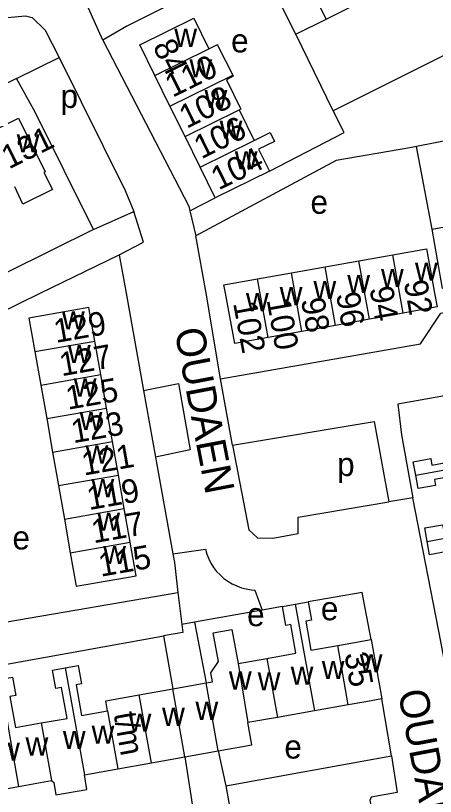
# Model space of a CAD drawing. Extents: x 157794 to 159375, y 380877 to 382306.
# Drawn here: x 158437 to 158508.3, y 381414.5 to 381547.1 of the extents above; entities that cross this region are included whole.
import ezdxf

# ---------------------------------------------------------------- set-up
doc = ezdxf.new("R2010")
doc.units = 0
for name, color, linetype in [('BLT_Basislijn', 7, 'Continuous'), ('BLT_Bebouwing', 7, 'Continuous'), ('BLT_Centroide', 7, 'Continuous'), ('BLT_Huisnummer', 7, 'Continuous'), ('BLT_Huisnummer_ tussenligend', 7, 'Continuous'), ('BLT_Huisnummer_reeks', 7, 'Continuous'), ('BLT_Onderverdeling_panden', 7, 'Continuous'), ('BLT_Straatnaam', 7, 'Continuous')]:
    doc.layers.add(name, color=color, linetype=linetype)

msp = doc.modelspace()

# ---------------------------------------------------------------- linework, layer by layer
at = {"layer": 'BLT_Basislijn'}
for p, q in [((158519.87, 381545.44), (158490.95, 381530.99)), ((158490.95, 381530.99), (158484.57, 381543.99)), ((158437.14, 381536.48), (158444.4, 381540.04)), ((158524.33, 381528.74), (158505.11, 381524.89)), ((158507.73, 381510.87), (158505.11, 381524.89)), ((158466.62, 381513.98), (158470.92, 381516.18)), ((158450.23, 381510.78), (158457.08, 381513.88)), ((158466.62, 381513.98), (158467.63, 381509.74)), ((158473.82, 381474.14), (158471.81, 381485.4)), ((158458.75, 381483.43), (158460.77, 381472.12)), ((158460.77, 381472.12), (158463.72, 381455.67)), ((158504.49, 381465.23), (158500.38, 381464.53)), ((158463.72, 381455.67), (158469.25, 381456.46)), ((158464.58, 381449.11), (158465.22, 381443.65)), ((158477.65, 381449.54), (158478.89, 381446.13)), ((158482.31, 381446.75), (158478.89, 381446.13)), ((158478.89, 381446.13), (158467.4, 381444.05)), ((158467.4, 381444.05), (158465.22, 381443.65)), ((158467.4, 381444.05), (158469.36, 381433.75)), ((158462.15, 381441.73), (158463.68, 381432.73)), ((158500.87, 381421.37), (158499.19, 381431.02)), ((158465.74, 381421.18), (158467.36, 381410.72)), ((158471.43, 381422.2), (158472.71, 381416.28)), ((158472.71, 381416.28), (158500.87, 381421.37))]:
    msp.add_line(p, q, dxfattribs=at)
for points in [[(158451.81, 381542.95), (158449.11, 381549.01), (158449.43, 381551.81), (158451.61, 381553.86), (158561.13, 381600.93)], [(158478.22, 381556.59), (158477.09, 381556.02), (158455.91, 381545.38), (158451.81, 381542.95)], [(158432.05, 381545.11), (158435.65, 381546.85), (158438.67, 381547.13), (158439.79, 381546.85), (158442.01, 381544.7), (158444.4, 381540.04)], [(158451.81, 381542.95), (158466.43, 381514.78), (158466.62, 381513.98)], [(158444.4, 381540.04), (158455.63, 381517.4), (158457.08, 381513.88)], [(158437.14, 381536.48), (158402.44, 381519.39), (158402.32, 381519.33)], [(158450.23, 381510.78), (158440.35, 381530.76), (158437.14, 381536.48)], [(158480.1, 381520.71), (158492.78, 381527.28), (158490.95, 381530.99)], [(158505.11, 381524.89), (158503.95, 381524.66), (158491.43, 381522.5), (158467.63, 381509.74)], [(158454.58, 381506.47), (158458.75, 381508.66), (158457.08, 381513.88)], [(158450.23, 381510.78), (158428.38, 381500), (158416.79, 381493.84)], [(158471.81, 381485.4), (158469.37, 381500), (158467.63, 381509.74)], [(158428.64, 381479.68), (158426.62, 381492.06), (158426.74, 381492.89), (158441.15, 381500), (158454.58, 381506.47)], [(158454.58, 381506.47), (158455.78, 381500), (158458.75, 381483.43)], [(158471.81, 381485.4), (158505.79, 381491.35), (158509.22, 381496.6), (158527.38, 381500), (158562.57, 381506.47)], [(158529.66, 381491.41), (158517.05, 381489.15), (158513.32, 381484.4), (158511.45, 381482.81), (158501.9, 381481.1), (158502.53, 381475.91), (158504.49, 381465.23)], [(158458.75, 381483.43), (158464.65, 381484.62), (158466.65, 381473.34), (158460.77, 381472.12)], [(158473.82, 381474.14), (158497.89, 381478.15), (158500.38, 381464.53)], [(158473.82, 381474.14), (158476.63, 381459.78), (158478.07, 381458.43), (158480.71, 381458.36), (158485, 381459.16), (158484.98, 381461.91), (158500.38, 381464.53)], [(158516.54, 381401.63), (158509.27, 381440.5), (158504.49, 381465.23)], [(158463.72, 381455.67), (158463.98, 381454.24), (158464.58, 381449.11)], [(158469.25, 381456.46), (158469.49, 381455.64), (158469.8, 381454.85), (158470.18, 381454.1), (158470.64, 381453.38), (158471.15, 381452.71), (158471.74, 381452.09), (158472.37, 381451.52), (158473.06, 381451.02), (158473.79, 381450.59), (158474.55, 381450.22), (158475.35, 381449.93), (158476.17, 381449.72), (158477.01, 381449.59), (158477.65, 381449.54)], [(158434.46, 381449.35), (158435.52, 381444.13), (158464.58, 381449.11)], [(158497.38, 381441.14), (158495.88, 381449.11), (158486.67, 381447.53)], [(158465.22, 381443.65), (158465.38, 381442.34), (158462.15, 381441.73)], [(158404.63, 381433.72), (158404.24, 381435.67), (158426.55, 381439.67), (158427.12, 381439.4), (158428.2, 381435.71), (158428.84, 381435.74), (158461.58, 381441.62), (158462.15, 381441.73)], [(158500.87, 381421.37), (158501.78, 381415.14), (158497.38, 381414.35), (158497.19, 381413.77), (158498.73, 381406.43)], [(158472.71, 381416.28), (158474.45, 381406.5), (158472.22, 381406.1), (158472.99, 381401.84)]]:
    msp.add_lwpolyline(points, dxfattribs=at)
at = {"layer": 'BLT_Bebouwing'}
for p, q in [((158489.75, 381546.57), (158494.93, 381549.15)), ((158484.57, 381543.99), (158489.75, 381546.57)), ((158463.22, 381531.78), (158460.66, 381536.98)), ((158465.79, 381526.58), (158463.22, 381531.78)), ((158474.97, 381531.11), (158477.54, 381525.91)), ((158468.35, 381521.38), (158465.79, 381526.58)), ((158470.92, 381516.18), (158468.35, 381521.38)), ((158480.1, 381520.71), (158470.92, 381516.18)), ((158507.73, 381510.87), (158513.4, 381511.87)), ((158495.32, 381505.49), (158501.05, 381506.51)), ((158489.58, 381504.47), (158495.32, 381505.49)), ((158478.11, 381502.44), (158483.84, 381503.46)), ((158483.84, 381503.46), (158489.58, 381504.47)), ((158497.08, 381495.55), (158491.35, 381494.51)), ((158502.81, 381496.59), (158497.08, 381495.55)), ((158491.35, 381494.51), (158485.61, 381493.47)), ((158485.61, 381493.47), (158479.88, 381492.44)), ((158451.47, 381486.15), (158450.46, 381491.85)), ((158440.28, 381490.06), (158441.28, 381484.36)), ((158452.47, 381480.46), (158451.47, 381486.15)), ((158441.28, 381484.36), (158442.29, 381478.67)), ((158453.47, 381474.76), (158452.47, 381480.46)), ((158442.29, 381478.67), (158443.29, 381472.97)), ((158454.47, 381469.06), (158453.47, 381474.76)), ((158443.29, 381472.97), (158444.29, 381467.27)), ((158455.47, 381463.37), (158454.47, 381469.06)), ((158444.29, 381467.27), (158445.29, 381461.58)), ((158456.47, 381457.67), (158455.47, 381463.37)), ((158445.29, 381461.58), (158446.29, 381455.88)), ((158482.31, 381446.75), (158484.49, 381447.14)), ((158484.49, 381447.14), (158486.67, 381447.53)), ((158491.72, 381440.13), (158497.38, 381441.14)), ((158497.38, 381441.14), (158499.19, 381431.02)), ((158474.79, 381437.04), (158479.69, 381437.91)), ((158463.68, 381432.73), (158469.36, 381433.75)), ((158457.99, 381431.72), (158463.68, 381432.73)), ((158493.5, 381430.01), (158487.74, 381429)), ((158481.48, 381427.9), (158476.43, 381427.02)), ((158487.74, 381429), (158481.48, 381427.9)), ((158460.06, 381420.16), (158465.74, 381421.18)), ((158465.74, 381421.18), (158471.43, 381422.2)), ((158454.38, 381419.15), (158460.06, 381420.16)), ((158448.69, 381418.13), (158454.38, 381419.15)), ((158437.5, 381416.13), (158443.12, 381417.14))]:
    msp.add_line(p, q, dxfattribs=at)
for points in [[(158484.57, 381543.99), (158484.04, 381545.06), (158482.33, 381548.5), (158480.07, 381553.05)], [(158460.66, 381536.98), (158458.09, 381542.18), (158467.27, 381546.71), (158469.83, 381541.51)], [(158469.83, 381541.51), (158471.28, 381542.21), (158471.37, 381542.02), (158473.89, 381537)], [(158473.89, 381537), (158473.96, 381536.84), (158472.8, 381536.26), (158475.23, 381531.24), (158474.97, 381531.11)], [(158432.35, 381527.15), (158437.52, 381529.73), (158442.05, 381520.62), (158441.81, 381520.5), (158443.25, 381517.6), (158438.24, 381515.11), (158436.88, 381518.05)], [(158477.54, 381525.91), (158480.23, 381527.26), (158480.95, 381525.75), (158478.27, 381524.43), (158480.1, 381520.71)], [(158515.2, 381501.75), (158509.52, 381500.75), (158508.65, 381505.67), (158507.73, 381510.87)], [(158501.05, 381506.51), (158506.79, 381507.53), (158507.7, 381502.55), (158508.15, 381500), (158508.59, 381497.64), (158502.81, 381496.59)], [(158479.88, 381492.44), (158474.23, 381491.41), (158472.63, 381500), (158472.37, 381501.42), (158478.11, 381502.44)], [(158450.46, 381491.85), (158449.46, 381497.55), (158439.28, 381495.76), (158440.28, 381490.06)], [(158504.95, 381469.06), (158504.54, 381471.32), (158507.51, 381471.86), (158507.71, 381470.76), (158512.84, 381471.69), (158511.91, 381476.82)], [(158514.08, 381464.85), (158513.28, 381469.23), (158508.13, 381468.29), (158508.31, 381467.32), (158505.37, 381466.79), (158504.95, 381469.06)], [(158506.9, 381457.81), (158506.49, 381460.08), (158509.52, 381460.63), (158509.72, 381459.53), (158514.87, 381460.46), (158514.08, 381464.85)], [(158446.29, 381455.88), (158447.29, 381450.18), (158457.47, 381451.97), (158456.47, 381457.67)], [(158516.08, 381453.58), (158515.29, 381457.93), (158510.16, 381456.99), (158510.32, 381456.08), (158507.32, 381455.53), (158506.9, 381457.81)], [(158479.69, 381437.91), (158484.59, 381438.79), (158483.72, 381443.68), (158482.89, 381443.53), (158482.31, 381446.75)], [(158486.67, 381447.53), (158487.23, 381444.4), (158486.27, 381444.22), (158487.15, 381439.31), (158491.72, 381440.13)], [(158469.36, 381433.75), (158470.43, 381433.94), (158470.15, 381435.49), (158471.46, 381437.37), (158470.58, 381442.26), (158473.75, 381442.82), (158474.79, 381437.04)], [(158441.37, 381426.94), (158445.76, 381427.73), (158444.82, 381432.98), (158443.81, 381432.8), (158443.25, 381435.93), (158445.44, 381436.32)], [(158445.44, 381436.32), (158447.62, 381436.71), (158448.18, 381433.58), (158447.27, 381433.42), (158448.2, 381428.2), (158452.62, 381428.99)], [(158434.25, 381434.31), (158436.48, 381434.71), (158437.03, 381431.61), (158436.04, 381431.43), (158436.98, 381426.16), (158441.37, 381426.94)], [(158452.62, 381428.99), (158452.31, 381430.7), (158457.99, 381431.72)], [(158499.19, 381431.02), (158496.47, 381430.53), (158493.5, 381430.01)], [(158471.43, 381422.2), (158477.11, 381423.21), (158476.43, 381427.02)], [(158431.31, 381418.84), (158431.97, 381415.14), (158437.5, 381416.13)], [(158443.12, 381417.14), (158443.48, 381416.83), (158443.86, 381414.71), (158449.09, 381415.65), (158448.69, 381418.13)]]:
    msp.add_lwpolyline(points, dxfattribs=at)
at = {"layer": 'BLT_Onderverdeling_panden'}
for p, q in [((158489.75, 381546.57), (158485.25, 381555.62)), ((158460.66, 381536.98), (158469.83, 381541.51)), ((158463.22, 381531.78), (158473.89, 381537)), ((158465.79, 381526.58), (158474.97, 381531.11)), ((158468.35, 381521.38), (158477.54, 381525.91)), ((158502.81, 381496.59), (158501.05, 381506.51)), ((158497.08, 381495.55), (158495.32, 381505.49)), ((158485.61, 381493.47), (158483.84, 381503.46)), ((158491.35, 381494.51), (158489.58, 381504.47)), ((158479.88, 381492.44), (158478.11, 381502.44)), ((158440.28, 381490.06), (158450.46, 381491.85)), ((158441.28, 381484.36), (158451.47, 381486.15)), ((158442.29, 381478.67), (158452.47, 381480.46)), ((158443.29, 381472.97), (158453.47, 381474.76)), ((158504.95, 381469.06), (158522.94, 381472.32)), ((158444.29, 381467.27), (158454.47, 381469.06)), ((158445.29, 381461.58), (158455.47, 381463.37)), ((158506.9, 381457.81), (158524.98, 381461.09)), ((158446.29, 381455.88), (158456.47, 381457.67)), ((158484.49, 381447.14), (158487.74, 381429)), ((158493.5, 381430.01), (158491.72, 381440.13)), ((158479.69, 381437.91), (158481.48, 381427.9)), ((158445.44, 381436.32), (158448.69, 381418.13)), ((158474.79, 381437.04), (158476.43, 381427.02)), ((158434.25, 381434.31), (158437.5, 381416.13)), ((158471.43, 381422.2), (158469.36, 381433.75)), ((158465.74, 381421.18), (158463.68, 381432.73)), ((158460.06, 381420.16), (158457.99, 381431.72)), ((158452.62, 381428.99), (158454.38, 381419.15)), ((158441.37, 381426.94), (158443.12, 381417.14))]:
    msp.add_line(p, q, dxfattribs=at)

# ---------------------------------------------------------------- texts
at = {"layer": 'BLT_Centroide'}
for s, p in [('w', (158463.96, 381541.84)), ('e', (158473.6, 381540.89)), ('w', (158466.53, 381536.66)), ('p', (158444.64, 381531.46)), ('w', (158469.09, 381531.44)), ('w', (158471.66, 381526.25)), ('w', (158437.2, 381523.89)), ('w', (158474.23, 381521.03)), ('e', (158487.08, 381513.47)), ('w', (158504.83, 381502.08)), ('w', (158499.06, 381501.03)), ('w', (158493.33, 381500)), ('w', (158481.86, 381497.94)), ('w', (158487.59, 381498.98)), ('w', (158476.12, 381496.92)), ('w', (158444.88, 381493.81)), ('w', (158445.88, 381488.09)), ('w', (158446.88, 381482.41)), ('w', (158447.88, 381476.72)), ('w', (158448.88, 381471.03)), ('p', (158491.6, 381468.91)), ('w', (158449.88, 381465.31)), ('w', (158450.88, 381459.62)), ('e', (158436.47, 381456.43)), ('w', (158451.88, 381453.94)), ('e', (158476.32, 381443.39)), ('e', (158488.85, 381444.4)), ('w', (158495.45, 381435.56)), ('w', (158489, 381434.42)), ('w', (158483.72, 381433.45)), ('w', (158473.23, 381432.62)), ('w', (158478.12, 381432.47)), ('w', (158467.55, 381427.47)), ('w', (158461.88, 381426.45)), ('w', (158456.19, 381425.44)), ('w', (158449.91, 381423.42)), ('w', (158445.03, 381422.53)), ('w', (158438.69, 381421.41)), ('e', (158482.65, 381420.9)), ('w', (158433.86, 381420.52))]:
    msp.add_text(s, height=4, dxfattribs=at).set_placement(p)
at = {"layer": 'BLT_Huisnummer'}
for s, rotation, p in [('84', 296.2571, (158460.22, 381541.94)), ('110', 26.2698, (158463.66, 381533.16)), ('131', 26.4579, (158435.88, 381520.99)), ('104', 26.2698, (158471.47, 381517.41)), ('92', 280.0617, (158502.92, 381501.88)), ('96', 280.0647, (158491.4, 381499.83)), ('102', 280.5999, (158473.93, 381498.28)), ('129', 9.9752, (158443.85, 381491.51)), ('123', 9.9752, (158446.81, 381474.47)), ('119', 9.9752, (158449.48, 381463.11)), ('115', 9.9752, (158451.46, 381451.78))]:
    msp.add_text(s, height=4, rotation=rotation, dxfattribs=at).set_placement(p)
at = {"layer": 'BLT_Huisnummer_ tussenligend'}
for s, rotation, p in [('108', 26.2698, (158466.06, 381527.88)), ('106', 26.2698, (158468.56, 381522.71)), ('94', 280.0617, (158497.09, 381500.83)), ('100', 280.0647, (158479.63, 381498.85)), ('98', 280.0647, (158485.45, 381498.89)), ('127', 9.9752, (158444.81, 381485.85)), ('125', 9.9752, (158445.89, 381480.16)), ('121', 9.9752, (158448.59, 381468.97)), ('117', 9.9752, (158450.25, 381457.47))]:
    msp.add_text(s, height=4, rotation=rotation, dxfattribs=at).set_placement(p)
at = {"layer": 'BLT_Huisnummer_reeks'}
for s, rotation, p in [('35', 279.9643, (158492.83, 381438.68)), ('t/m', 280.1388, (158453.63, 381428.49))]:
    msp.add_text(s, height=4, rotation=rotation, dxfattribs=at).set_placement(p)
at = {"layer": 'BLT_Straatnaam'}
for p in [(158463.98, 381493.66), (158501.93, 381432.22)]:
    msp.add_text('OUDAEN', height=5, rotation=280.7856, dxfattribs=at).set_placement(p)

doc.saveas('drawing.dxf')
